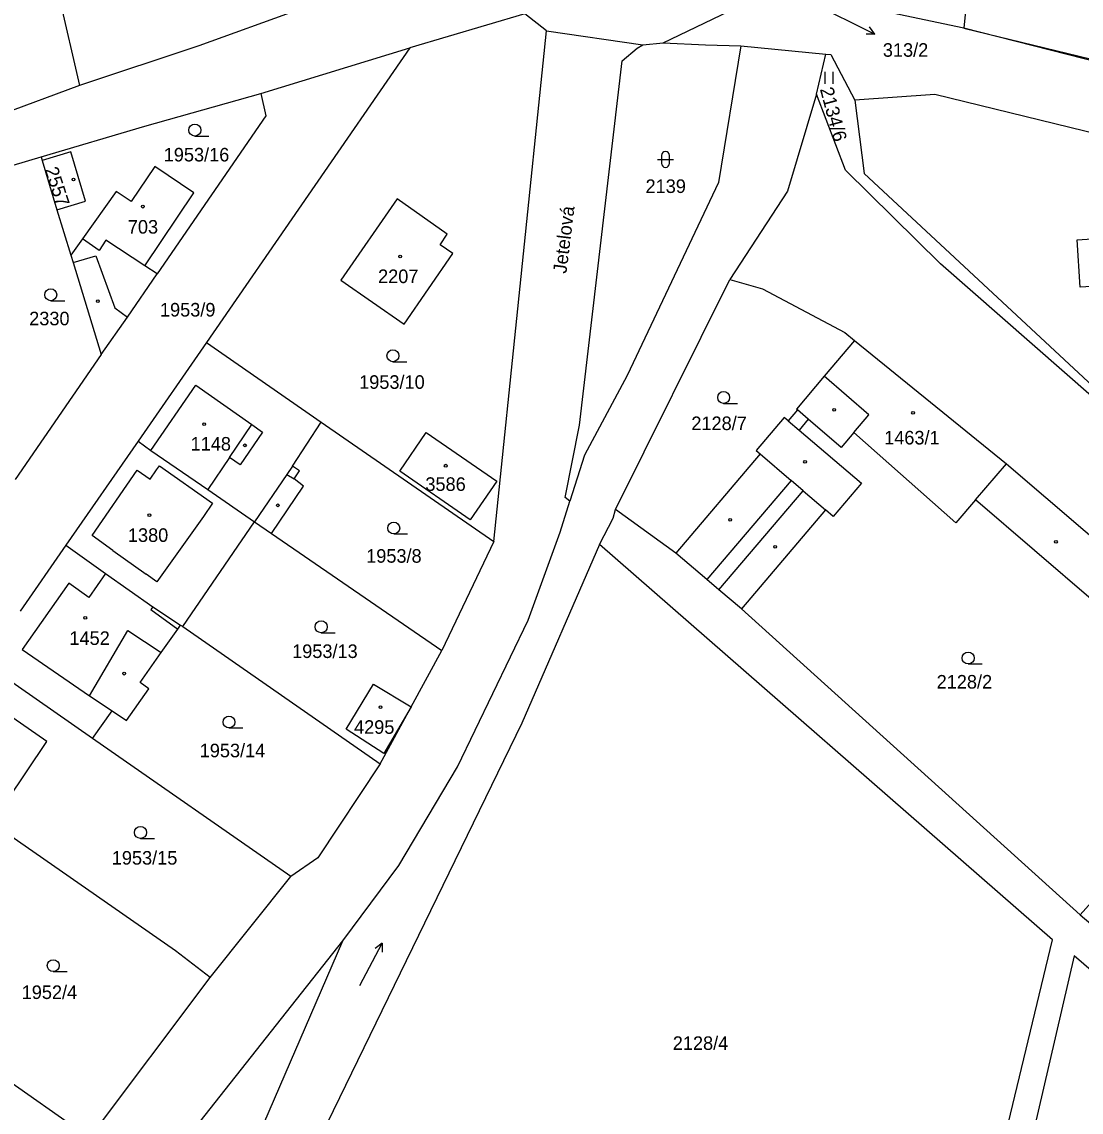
# Model space of a CAD drawing. Extents: x -679220 to -673243, y -1075091 to -1066557.
# Drawn here: x -676553.6 to -676420.8, y -1072700.8 to -1072564.1 of the extents above; entities that cross this region are included whole.
import ezdxf

# ---------------------------------------------------------------- set-up
doc = ezdxf.new("R2010")
doc.units = 0
for name, color, linetype in [('Hranice parcel', 7, 'Continuous'), ('Parcelní čísla', 7, 'Continuous'), ('Pop  PČ popisy', 7, 'Continuous'), ('Vnitřní kresba', 7, 'Continuous'), ('Značky budov', 7, 'Continuous'), ('Značky kultur', 7, 'Continuous')]:
    doc.layers.add(name, color=color, linetype=linetype)

msp = doc.modelspace()

# ---------------------------------------------------------------- linework, layer by layer
at = {"layer": 'Hranice parcel'}
for p, q in [((-676434.47, -1072553.84), (-676435.5, -1072564.92)), ((-676549.28, -1072559.4), (-676546.35, -1072572.11)), ((-676435.5, -1072564.92), (-676451.58, -1072561.54)), ((-676473.21, -1072566.78), (-676464.91, -1072562.82)), ((-676490.54, -1072563.15), (-676504.94, -1072567.41)), ((-676487.81, -1072565.29), (-676490.54, -1072563.15)), ((-676494.43, -1072629.26), (-676487.81, -1072565.29)), ((-676487.81, -1072565.29), (-676475.72, -1072567.03)), ((-676475.72, -1072567.03), (-676473.21, -1072566.78)), ((-676463.44, -1072567.15), (-676452.82, -1072568.19)), ((-676504.94, -1072567.41), (-676530.43, -1072604.34)), ((-676523.62, -1072573.14), (-676504.94, -1072567.41)), ((-676453.99, -1072573.19), (-676452.82, -1072568.19)), ((-676559.98, -1072583.7), (-676551.15, -1072581.08)), ((-676551.15, -1072581.08), (-676551.02, -1072581.53)), ((-676551.02, -1072581.53), (-676549.16, -1072587.68)), ((-676549.16, -1072587.68), (-676547.42, -1072593.38)), ((-676479.15, -1072625.24), (-676464.83, -1072596.41)), ((-676530.43, -1072604.34), (-676539, -1072616.68)), ((-676530.43, -1072604.34), (-676516.03, -1072614.31)), ((-676543.64, -1072605.83), (-676554.38, -1072621.51)), ((-676516.03, -1072614.31), (-676494.43, -1072629.26)), ((-676539, -1072616.68), (-676548.06, -1072629.7)), ((-676471.59, -1072630.74), (-676479.15, -1072625.24)), ((-676533.37, -1072639.93), (-676524.42, -1072626.79)), ((-676524.42, -1072626.79), (-676522.29, -1072628.27)), ((-676522.29, -1072628.27), (-676500.93, -1072642.94)), ((-676548.06, -1072629.7), (-676553.76, -1072637.97)), ((-676494.43, -1072629.26), (-676500.93, -1072642.94)), ((-676463.39, -1072637.7), (-676420.94, -1072676.03)), ((-676533.67, -1072639.73), (-676533.37, -1072639.93)), ((-676533.37, -1072639.93), (-676508.66, -1072657.14)), ((-676544.7, -1072653.95), (-676558.31, -1072644.47)), ((-676519.87, -1072671.24), (-676544.7, -1072653.95)), ((-676529.98, -1072683.88), (-676519.87, -1072671.24)), ((-676420.94, -1072676.03), (-676388.29, -1072703.96)), ((-676545.05, -1072703.94), (-676529.98, -1072683.88)), ((-676566.25, -1072689.13), (-676545.05, -1072703.94))]:
    msp.add_line(p, q, dxfattribs=at)
for points in [[(-676506.11, -1072557.33), (-676518.91, -1072562.62), (-676531.37, -1072567.13), (-676546.35, -1072572.11)], [(-676435.5, -1072564.92), (-676357.39, -1072583.92), (-676300.67, -1072598.66), (-676276.99, -1072604.89), (-676250.54, -1072613.43)], [(-676250.59, -1072614.34), (-676256.55, -1072612.46), (-676293.49, -1072601.38), (-676316.63, -1072595.38), (-676339.7, -1072589.69), (-676344.69, -1072588.09), (-676435.5, -1072564.92)], [(-676484.87, -1072624.22), (-676485.49, -1072623.75), (-676483.67, -1072614.69), (-676478.33, -1072569.05), (-676476.44, -1072567.44), (-676475.72, -1072567.03)], [(-676463.44, -1072567.15), (-676466.25, -1072584.28), (-676477.7, -1072608.48), (-676483.04, -1072618.46), (-676484.87, -1072624.22)], [(-676473.21, -1072566.78), (-676467.9, -1072567.03), (-676463.44, -1072567.15)], [(-676452.82, -1072568.19), (-676452.18, -1072568.25), (-676449.19, -1072573.94)], [(-676546.35, -1072572.11), (-676556.24, -1072575.81), (-676568.92, -1072579.9), (-676581.29, -1072583.45), (-676590.74, -1072586.31), (-676593.34, -1072586.97)], [(-676551.15, -1072581.08), (-676538.13, -1072577.22), (-676523.62, -1072573.14)], [(-676523.62, -1072573.14), (-676522.99, -1072575.93), (-676536.59, -1072595.73)], [(-676453.99, -1072573.19), (-676457.63, -1072585.36), (-676464.83, -1072596.41)], [(-676388.75, -1072638.01), (-676438.43, -1072594.48), (-676450.34, -1072582.75), (-676453.99, -1072573.19)], [(-676338.93, -1072598), (-676397.63, -1072583.39), (-676439.14, -1072573.25), (-676449.19, -1072573.94)], [(-676449.19, -1072573.94), (-676448, -1072583.14), (-676415.75, -1072613.12), (-676388.75, -1072638.01)], [(-676549.16, -1072587.68), (-676545.58, -1072586.6), (-676547.44, -1072580.45), (-676551.02, -1072581.53)], [(-676536.59, -1072595.73), (-676538.16, -1072594.71), (-676532, -1072585.58), (-676536.88, -1072582.25), (-676539.85, -1072586.66), (-676541.73, -1072585.4), (-676545.97, -1072591.34), (-676547.42, -1072593.38)], [(-676499.55, -1072593.19), (-676501.13, -1072592.08), (-676500.24, -1072590.76), (-676506.54, -1072586.31), (-676513.59, -1072596.52), (-676505.64, -1072602.01), (-676499.55, -1072593.19)], [(-676415.13, -1072597.05), (-676420.95, -1072597.39), (-676421.3, -1072591.46), (-676402.45, -1072590.19), (-676401.75, -1072598.85), (-676414.93, -1072599.83), (-676415.13, -1072597.05)], [(-676547.42, -1072593.38), (-676547.14, -1072594.31), (-676543.64, -1072605.83)], [(-676543.64, -1072605.83), (-676540.3, -1072601.15), (-676536.59, -1072595.73)], [(-676464.83, -1072596.41), (-676460.75, -1072597.61), (-676450.43, -1072603.08), (-676449.22, -1072604.06)], [(-676449.22, -1072604.06), (-676453, -1072608.55), (-676456.47, -1072612.67), (-676456.36, -1072612.77), (-676457.54, -1072614.15), (-676458.04, -1072613.73), (-676461.54, -1072617.84), (-676461.05, -1072618.26), (-676471.59, -1072630.74)], [(-676449.22, -1072604.06), (-676430.17, -1072619.51), (-676415.38, -1072632.2), (-676415.61, -1072632.46), (-676409.23, -1072637.98)], [(-676522.29, -1072628.27), (-676518.26, -1072622.33), (-676519.45, -1072621.4), (-676518.78, -1072620.41), (-676519.64, -1072619.82), (-676516.03, -1072614.31)], [(-676409.23, -1072637.98), (-676410.42, -1072639.39), (-676408.83, -1072640.74), (-676409.87, -1072641.98), (-676411.45, -1072640.61), (-676412.62, -1072641.99), (-676419.02, -1072636.48), (-676419.25, -1072636.72), (-676434.07, -1072624.05), (-676436.53, -1072626.92), (-676449.31, -1072615.62), (-676450.89, -1072617.48), (-676455, -1072613.94), (-676456.16, -1072615.32), (-676448.34, -1072621.94), (-676451.9, -1072626.14), (-676452.86, -1072625.31), (-676463.39, -1072637.7)], [(-676494.04, -1072621.72), (-676497.39, -1072626.54), (-676506.2, -1072620.43), (-676502.89, -1072615.61), (-676494.04, -1072621.72)], [(-676539, -1072616.68), (-676537.39, -1072617.85), (-676530.25, -1072622.75), (-676524.42, -1072626.79)], [(-676513.33, -1072679.29), (-676506.32, -1072669.87), (-676498.98, -1072657.49), (-676490.12, -1072639.11), (-676486.08, -1072628.11), (-676484.87, -1072624.22)], [(-676481.15, -1072629.62), (-676479.47, -1072626.33), (-676479.15, -1072625.24)], [(-676548.06, -1072629.7), (-676543.09, -1072633.28), (-676537.15, -1072637.43), (-676533.67, -1072639.73)], [(-676481.15, -1072629.62), (-676490.91, -1072652.02), (-676519.12, -1072709.94)], [(-676443.5, -1072758.41), (-676424.4, -1072679.18), (-676481.15, -1072629.62)], [(-676463.39, -1072637.7), (-676466.2, -1072635.32), (-676467.71, -1072634.03), (-676471.59, -1072630.74)], [(-676544.7, -1072653.95), (-676542.24, -1072650.48), (-676540.43, -1072651.69), (-676537.63, -1072647.73), (-676538.75, -1072646.94), (-676536.09, -1072643.16), (-676534.02, -1072640.23), (-676533.67, -1072639.73)], [(-676508.66, -1072657.14), (-676504.77, -1072649.98), (-676500.93, -1072642.94)], [(-676508.19, -1072655.81), (-676512.92, -1072652.79), (-676509.49, -1072647.15)], [(-676509.49, -1072647.15), (-676504.77, -1072649.98), (-676508.19, -1072655.81)], [(-676550.42, -1072654.33), (-676558.56, -1072648.68), (-676563.67, -1072656.02), (-676555.46, -1072661.8), (-676550.42, -1072654.33)], [(-676420.94, -1072676.03), (-676403.42, -1072656.5), (-676398.68, -1072659.96), (-676392.11, -1072651.77)], [(-676508.66, -1072657.14), (-676516.46, -1072668.9), (-676519.87, -1072671.24)], [(-676529.98, -1072683.88), (-676534.32, -1072680.56), (-676567.35, -1072657.57)], [(-676534.06, -1072705.55), (-676531.2, -1072701.92), (-676513.33, -1072679.29)], [(-676527.07, -1072711.02), (-676525.26, -1072706.83), (-676513.33, -1072679.29)], [(-676136.87, -1072926.75), (-676171.46, -1072897.09), (-676296.42, -1072789.24), (-676421.7, -1072681.18), (-676439.32, -1072757.23)]]:
    msp.add_lwpolyline(points, dxfattribs=at)
at = {"layer": 'Pop  PČ popisy'}
for p, q in [((-676452.05, -1072563.02), (-676449.35, -1072564.35)), ((-676449.35, -1072564.35), (-676446.65, -1072565.67)), ((-676446.65, -1072565.67), (-676447.77, -1072565.68)), ((-676446.65, -1072565.67), (-676447.33, -1072564.78))]:
    msp.add_line(p, q, dxfattribs=at)
at = {"layer": 'Vnitřní kresba'}
for p, q in [((-676543.87, -1072592.78), (-676545.97, -1072591.34)), ((-676543.05, -1072591.52), (-676543.87, -1072592.78)), ((-676538.16, -1072594.71), (-676543.05, -1072591.52)), ((-676547.14, -1072594.31), (-676544.28, -1072593.45)), ((-676544.28, -1072593.45), (-676541.92, -1072599.98)), ((-676541.92, -1072599.98), (-676540.3, -1072601.15)), ((-676447.4, -1072613.37), (-676453, -1072608.55)), ((-676537.39, -1072617.85), (-676531.76, -1072609.69)), ((-676531.76, -1072609.69), (-676524.74, -1072614.6)), ((-676455, -1072613.94), (-676456.36, -1072612.77)), ((-676449.31, -1072615.62), (-676447.4, -1072613.37)), ((-676527.55, -1072618.75), (-676524.74, -1072614.6)), ((-676524.74, -1072614.6), (-676523.4, -1072615.54)), ((-676457.54, -1072614.15), (-676456.16, -1072615.32)), ((-676523.4, -1072615.54), (-676526.19, -1072619.67)), ((-676527.55, -1072618.75), (-676530.25, -1072622.75)), ((-676526.19, -1072619.67), (-676527.55, -1072618.75)), ((-676461.05, -1072618.26), (-676457.17, -1072621.6)), ((-676544.74, -1072628.52), (-676539.11, -1072620.32)), ((-676539.11, -1072620.32), (-676537.5, -1072621.45)), ((-676537.5, -1072621.45), (-676536.69, -1072620.3)), ((-676536.69, -1072620.3), (-676536.31, -1072619.76)), ((-676536.31, -1072619.76), (-676529.67, -1072624.46)), ((-676519.64, -1072619.82), (-676520.36, -1072620.87)), ((-676434.07, -1072624.05), (-676430.17, -1072619.51)), ((-676520.36, -1072620.87), (-676524.42, -1072626.79)), ((-676520.36, -1072620.87), (-676519.45, -1072621.4)), ((-676457.17, -1072621.6), (-676467.71, -1072634.03)), ((-676455.63, -1072622.93), (-676457.17, -1072621.6)), ((-676466.2, -1072635.32), (-676455.63, -1072622.93)), ((-676455.63, -1072622.93), (-676452.86, -1072625.31)), ((-676529.67, -1072624.46), (-676530.81, -1072626.11)), ((-676530.81, -1072626.11), (-676536.65, -1072634.33)), ((-676542.14, -1072630.39), (-676544.74, -1072628.52)), ((-676542.14, -1072630.39), (-676537.98, -1072633.37)), ((-676543.09, -1072633.28), (-676545.16, -1072636.26)), ((-676536.65, -1072634.33), (-676537.98, -1072633.37)), ((-676547.69, -1072634.5), (-676553.52, -1072642.78)), ((-676545.16, -1072636.26), (-676547.69, -1072634.5)), ((-676537.15, -1072637.43), (-676537.41, -1072637.8)), ((-676537.41, -1072637.8), (-676534.02, -1072640.23)), ((-676545.08, -1072648.58), (-676540.28, -1072640.43)), ((-676540.28, -1072640.43), (-676536.09, -1072643.16)), ((-676553.52, -1072642.78), (-676545.08, -1072648.58)), ((-676545.08, -1072648.58), (-676542.24, -1072650.48))]:
    msp.add_line(p, q, dxfattribs=at)
at = {"layer": 'Značky budov'}
for centre in [(-676547.09, -1072583.89), (-676538.41, -1072587.3), (-676506.16, -1072593.54), (-676544.05, -1072599.14), (-676451.77, -1072612.77), (-676441.88, -1072613.15), (-676530.71, -1072614.56), (-676525.6, -1072617.21), (-676455.41, -1072619.29), (-676500.44, -1072619.76), (-676521.47, -1072624.73), (-676537.58, -1072625.96), (-676464.8, -1072626.55), (-676459.16, -1072629.94), (-676423.97, -1072629.31), (-676545.61, -1072638.82), (-676540.75, -1072645.82), (-676508.61, -1072650.02)]:
    msp.add_circle(centre, 0.175, dxfattribs=at)
at = {"layer": 'Značky kultur'}
for p, q in [((-676452.88, -1072571.91), (-676452.88, -1072570.41)), ((-676451.88, -1072571.91), (-676451.88, -1072570.41)), ((-676531.88, -1072578.45), (-676530.13, -1072578.45)), ((-676473.4, -1072580.88), (-676473.4, -1072581.88)), ((-676472.4, -1072581.88), (-676472.4, -1072580.88)), ((-676473.9, -1072581.38), (-676471.9, -1072581.38)), ((-676549.94, -1072599.09), (-676548.19, -1072599.09)), ((-676507.05, -1072606.73), (-676505.3, -1072606.73)), ((-676465.61, -1072611.96), (-676463.86, -1072611.96)), ((-676506.96, -1072628.32), (-676505.21, -1072628.32)), ((-676516.05, -1072640.7), (-676514.3, -1072640.7)), ((-676434.97, -1072644.61), (-676433.22, -1072644.61)), ((-676527.6, -1072652.63), (-676525.85, -1072652.63)), ((-676538.69, -1072666.47), (-676536.94, -1072666.47)), ((-676511.21, -1072684.91), (-676508.4, -1072679.61)), ((-676508.4, -1072679.61), (-676509.3, -1072680.24)), ((-676508.4, -1072679.61), (-676508.41, -1072680.71)), ((-676549.63, -1072683.16), (-676547.88, -1072683.16))]:
    msp.add_line(p, q, dxfattribs=at)
for centre in [(-676531.88, -1072577.7), (-676549.94, -1072598.34), (-676507.05, -1072605.98), (-676465.61, -1072611.21), (-676506.96, -1072627.57), (-676516.05, -1072639.95), (-676434.97, -1072643.86), (-676527.6, -1072651.88), (-676538.69, -1072665.72), (-676549.63, -1072682.41)]:
    msp.add_circle(centre, 0.75, dxfattribs=at)
for centre, start, end in [((-676472.9, -1072580.88), 0, 180), ((-676472.9, -1072581.88), 180, 359.9879)]:
    msp.add_arc(centre, 0.5, start, end, dxfattribs=at)

# ---------------------------------------------------------------- texts
at = {"layer": 'Parcelní čísla'}
for s, p in [('313/2', (-676445.66, -1072568.52)), ('1953/16', (-676535.78, -1072581.64)), ('2139', (-676475.4, -1072585.59)), ('703', (-676540.28, -1072590.68)), ('2207', (-676508.92, -1072596.88)), ('1953/9', (-676536.25, -1072601.07)), ('2330', (-676552.64, -1072602.17)), ('1953/10', (-676511.29, -1072610.13)), ('2128/7', (-676469.66, -1072615.3)), ('1148', (-676532.41, -1072617.87)), ('1463/1', (-676445.5, -1072617.1)), ('3586', (-676502.99, -1072622.92)), ('1380', (-676540.27, -1072629.31)), ('1953/8', (-676510.41, -1072631.92)), ('1452', (-676547.6, -1072642.22)), ('1953/13', (-676519.69, -1072643.86)), ('2128/2', (-676438.92, -1072647.69)), ('4295', (-676511.93, -1072653.36)), ('1953/14', (-676531.27, -1072656.3)), ('1953/15', (-676542.29, -1072669.75)), ('1952/4', (-676553.58, -1072686.59)), ('2128/4', (-676471.99, -1072692.97))]:
    msp.add_text(s, height=1.7, dxfattribs=at).set_placement(p)
for s, rotation, p in [('2134/6', 285, (-676453.56, -1072572.57)), ('2557', 288, (-676550.71, -1072582.63))]:
    msp.add_text(s, height=1.7, rotation=rotation, dxfattribs=at).set_placement(p)
at = {"layer": 'Pop  PČ popisy'}
msp.add_text('Jetelová', height=1.7, rotation=83, dxfattribs=at).set_placement((-676485.32, -1072595.74))

doc.saveas('drawing.dxf')
